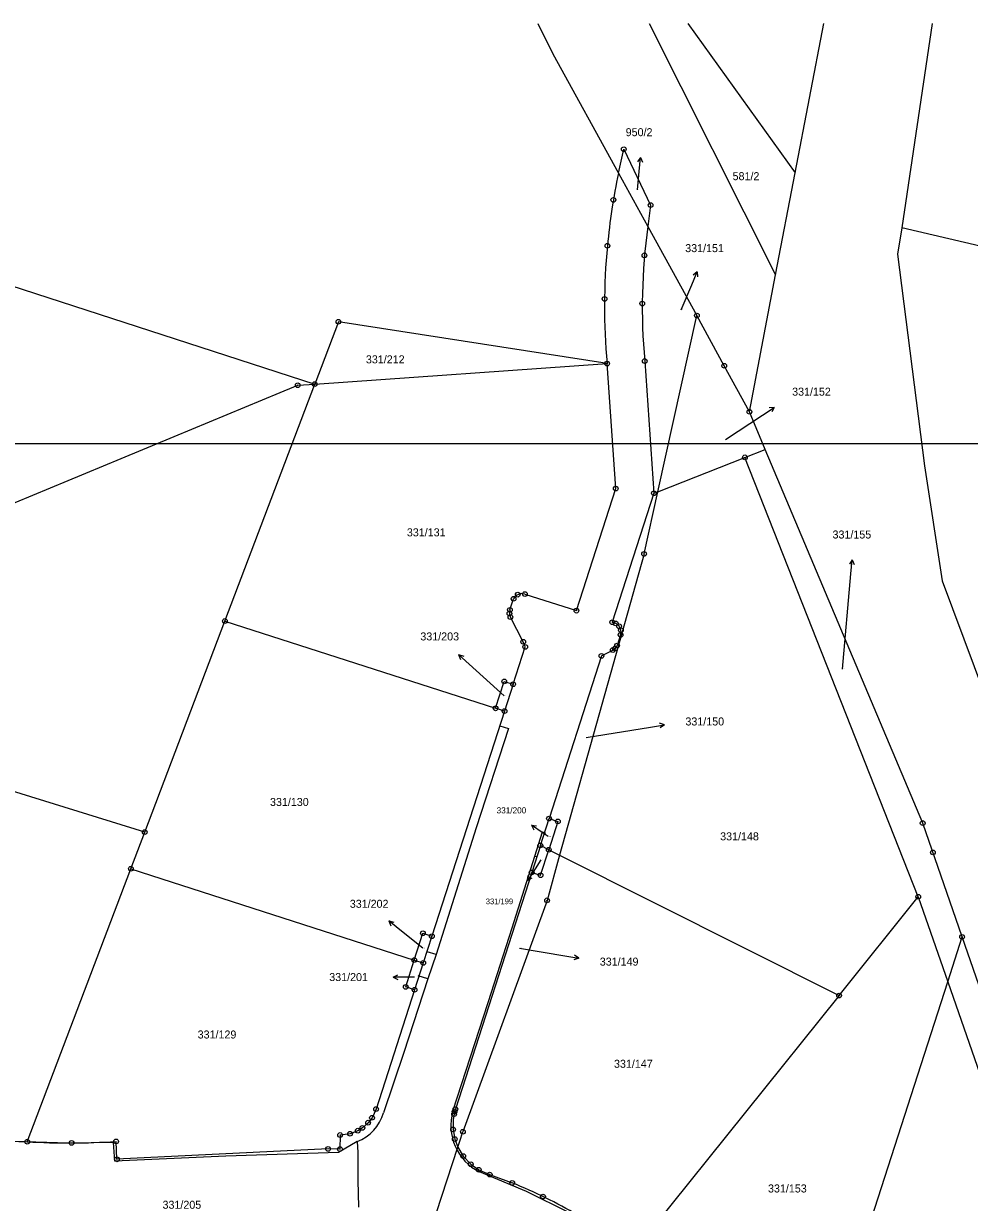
# Model space of a CAD drawing. Extents: x -770973 to -770265, y -1049936 to -1049427.
# Drawn here: x -770738 to -770637.6, y -1049553.2 to -1049428.1 of the extents above; entities that cross this region are included whole.
import ezdxf

# ---------------------------------------------------------------- set-up
doc = ezdxf.new("R2010")
doc.units = 0
for name, color, linetype in [('Vrstva 1', 7, 'Continuous'), ('Vrstva 13', 7, 'Continuous'), ('Vrstva 14', 7, 'Continuous'), ('Vrstva 16', 7, 'Continuous'), ('Vrstva 28', 7, 'Continuous'), ('Vrstva 50', 7, 'Continuous'), ('Vrstva 63', 7, 'Continuous')]:
    doc.layers.add(name, color=color, linetype=linetype)

msp = doc.modelspace()

# ---------------------------------------------------------------- linework, layer by layer
at = {"layer": 'Vrstva 1'}
for p, q in [((-770683.41, -1049428.06), (-770681.81, -1049431.27)), ((-770671.59, -1049428.06), (-770658.16, -1049454.74)), ((-770667.47, -1049428.06), (-770656.09, -1049443.91)), ((-770656.09, -1049443.91), (-770653.05, -1049428.06)), ((-770641.53, -1049428.06), (-770644.75, -1049449.76)), ((-770681.81, -1049431.27), (-770674.84, -1049443.93)), ((-770674.84, -1049443.93), (-770674.27, -1049441.4)), ((-770674.27, -1049441.4), (-770671.42, -1049447.33)), ((-770674.84, -1049443.93), (-770671.72, -1049449.6)), ((-770658.16, -1049454.74), (-770656.09, -1049443.91)), ((-770763.77, -1049447.98), (-770707.08, -1049466.34)), ((-770671.42, -1049447.33), (-770671.72, -1049449.6)), ((-770671.72, -1049449.6), (-770666.51, -1049459.06)), ((-770644.75, -1049449.76), (-770645.2, -1049452.54)), ((-770613.78, -1049456.97), (-770644.75, -1049449.76)), ((-770645.2, -1049452.54), (-770642.33, -1049475.02)), ((-770660.94, -1049469.28), (-770658.16, -1049454.74)), ((-770670.66, -1049477.77), (-770666.51, -1049459.06)), ((-770663.6, -1049464.4), (-770666.51, -1049459.06)), ((-770704.57, -1049459.72), (-770707.08, -1049466.34)), ((-770676.04, -1049464.17), (-770704.57, -1049459.72)), ((-770707.08, -1049466.34), (-770676.04, -1049464.17)), ((-770675.12, -1049477.44), (-770676.04, -1049464.17)), ((-770672.05, -1049463.89), (-770671.07, -1049477.93)), ((-770660.94, -1049469.28), (-770663.6, -1049464.4)), ((-770781.42, -1049496.53), (-770708.89, -1049466.46)), ((-770716.62, -1049491.5), (-770707.08, -1049466.34)), ((-770708.89, -1049466.46), (-770707.08, -1049466.34)), ((-770659.26, -1049473.27), (-770660.94, -1049469.28)), ((-770661.42, -1049474.12), (-770659.26, -1049473.27)), ((-770642.54, -1049512.96), (-770659.26, -1049473.27)), ((-770670.66, -1049477.77), (-770661.42, -1049474.12)), ((-770643.01, -1049520.78), (-770661.42, -1049474.12)), ((-770642.33, -1049475.02), (-770640.48, -1049487.25)), ((-770679.3, -1049490.4), (-770675.12, -1049477.44)), ((-770671.07, -1049477.93), (-770675.49, -1049491.63)), ((-770672.12, -1049484.38), (-770670.66, -1049477.77)), ((-770671.07, -1049477.93), (-770670.66, -1049477.77)), ((-770672.12, -1049484.38), (-770681.08, -1049516.37)), ((-770640.48, -1049487.25), (-770634.36, -1049503.66)), ((-770686.36, -1049490.32), (-770685.97, -1049489.14)), ((-770684.77, -1049488.64), (-770679.3, -1049490.4)), ((-770725.13, -1049513.91), (-770716.62, -1049491.5)), ((-770716.62, -1049491.5), (-770687.88, -1049500.77)), ((-770684.95, -1049493.71), (-770686.3, -1049491.08)), ((-770674.61, -1049492.97), (-770674.98, -1049494.11)), ((-770686.02, -1049498.21), (-770684.74, -1049494.25)), ((-770684.74, -1049494.25), (-770684.95, -1049493.71)), ((-770676.64, -1049495.2), (-770675.44, -1049494.58)), ((-770676.64, -1049495.2), (-770682.21, -1049512.48)), ((-770687.88, -1049500.77), (-770686.96, -1049497.91)), ((-770686.96, -1049497.91), (-770686.02, -1049498.21)), ((-770686.02, -1049498.21), (-770686.93, -1049501.07)), ((-770686.93, -1049501.07), (-770687.88, -1049500.77)), ((-770686.93, -1049501.07), (-770694.65, -1049524.97)), ((-770725.13, -1049513.91), (-770758.02, -1049503.75)), ((-770683.13, -1049515.33), (-770682.21, -1049512.48)), ((-770681.27, -1049512.78), (-770682.23, -1049515.79)), ((-770682.21, -1049512.48), (-770681.27, -1049512.78)), ((-770638.35, -1049525.05), (-770642.54, -1049512.96)), ((-770726.6, -1049517.8), (-770725.13, -1049513.91)), ((-770683.13, -1049515.33), (-770684.05, -1049518.19)), ((-770682.23, -1049515.79), (-770683.13, -1049515.33)), ((-770683.1, -1049518.49), (-770682.23, -1049515.79)), ((-770682.23, -1049515.79), (-770681.08, -1049516.37)), ((-770681.08, -1049516.37), (-770682.42, -1049521.16)), ((-770681.08, -1049516.37), (-770651.42, -1049531.27)), ((-770737.6, -1049546.8), (-770726.6, -1049517.8)), ((-770726.6, -1049517.8), (-770696.51, -1049527.5)), ((-770684.05, -1049518.19), (-770692.15, -1049543.32)), ((-770684.05, -1049518.19), (-770683.1, -1049518.49)), ((-770651.42, -1049531.27), (-770643.01, -1049520.78)), ((-770643.01, -1049520.78), (-770639.88, -1049529.8)), ((-770682.42, -1049521.16), (-770691.35, -1049545.73)), ((-770696.51, -1049527.5), (-770695.6, -1049524.66)), ((-770695.6, -1049524.66), (-770694.65, -1049524.97)), ((-770694.65, -1049524.97), (-770695.56, -1049527.8)), ((-770639.88, -1049529.8), (-770638.35, -1049525.05)), ((-770629.03, -1049551.97), (-770638.35, -1049525.05)), ((-770697.42, -1049530.36), (-770696.51, -1049527.5)), ((-770696.51, -1049527.5), (-770695.56, -1049527.8)), ((-770695.56, -1049527.8), (-770696.48, -1049530.66)), ((-770696.48, -1049530.66), (-770700.56, -1049543.32)), ((-770696.48, -1049530.66), (-770697.42, -1049530.36)), ((-770652.75, -1049569.77), (-770639.88, -1049529.8)), ((-770639.88, -1049529.8), (-770631.77, -1049553.2)), ((-770651.42, -1049531.27), (-770673.36, -1049558.61)), ((-770700.56, -1049543.32), (-770701, -1049544.25)), ((-770701, -1049544.25), (-770701.41, -1049544.77)), ((-770692.39, -1049544.43), (-770692.4, -1049545.48)), ((-770692.28, -1049543.86), (-770692.39, -1049544.43)), ((-770703.33, -1049545.94), (-770704.39, -1049546.08)), ((-770702.51, -1049545.62), (-770703.33, -1049545.94)), ((-770702.02, -1049545.32), (-770702.51, -1049545.62)), ((-770701.41, -1049544.77), (-770702.02, -1049545.32)), ((-770692.4, -1049545.48), (-770692.21, -1049546.51)), ((-770691.69, -1049546.75), (-770691.35, -1049545.73)), ((-770728.08, -1049548.66), (-770728.17, -1049546.76)), ((-770704.39, -1049546.08), (-770704.4, -1049547.58)), ((-770692.21, -1049546.51), (-770691.9, -1049547.38)), ((-770691.9, -1049547.38), (-770691.69, -1049546.75)), ((-770705.66, -1049547.56), (-770728.08, -1049548.66)), ((-770704.4, -1049547.58), (-770705.66, -1049547.56)), ((-770694.96, -1049556.73), (-770691.9, -1049547.38)), ((-770691.9, -1049547.38), (-770691.31, -1049548.32)), ((-770691.31, -1049548.32), (-770690.51, -1049549.18)), ((-770690.51, -1049549.18), (-770689.67, -1049549.77)), ((-770689.67, -1049549.77), (-770688.51, -1049550.28)), ((-770688.51, -1049550.28), (-770686.12, -1049551.16))]:
    msp.add_line(p, q, dxfattribs=at)
for centre, radius, start, end in [((-770609.84, -1049457.72), 66.44, 168.0204, 174.7659), ((-770609.76, -1049458.18), 62.55, 172.116, 185.2382), ((-770608.57, -1049458.08), 67.75, 174.5651, 185.1601), ((-770685.08, -1049489.59), 1, 72.1339, 153.1059), ((-770685.46, -1049490.63), 0.951, 160.8738, 208.1542), ((-770675.67, -1049492.76), 1.14, 38.3729, 81.1142), ((-770675.5, -1049492.65), 0.945, 340.255, 39.4766), ((-770675.83, -1049493.74), 0.926, 294.8238, 336.4083), ((-770689.65, -1049544.21), 2.65, 160.4513, 172.477), ((-770733.4, -1049469.63), 77.29, 256.2526, 266.8876), ((-770733.22, -1049467.42), 79.5, 266.8431, 273.643), ((-770705.43, -1049599.12), 51.7, 59.4615, 68.0688)]:
    msp.add_arc(centre, radius, start, end, dxfattribs=at)
at = {"layer": 'Vrstva 13'}
for p, q in [((-770672.82, -1049445.71), (-770672.64, -1049443.76)), ((-770668.19, -1049458.47), (-770667.05, -1049455.79)), ((-770663.48, -1049472.21), (-770659.54, -1049469.63)), ((-770651.05, -1049496.6), (-770650.15, -1049486.48)), ((-770686.98, -1049499.46), (-770690.7, -1049496.08)), ((-770678.28, -1049503.88), (-770671.43, -1049502.77)), ((-770682.29, -1049514.39), (-770682.84, -1049514.02)), ((-770683.08, -1049516.85), (-770683.69, -1049517.8)), ((-770695.61, -1049526.24), (-770698.05, -1049524.29)), ((-770685.35, -1049526.25), (-770680.52, -1049527.05)), ((-770696.5, -1049529.31), (-770697.26, -1049529.31))]:
    msp.add_line(p, q, dxfattribs=at)
at = {"layer": 'Vrstva 16'}
for p, q in [((-770672.51, -1049442.27), (-770672.8, -1049442.74)), ((-770672.64, -1049443.76), (-770672.51, -1049442.27)), ((-770672.51, -1049442.27), (-770672.3, -1049442.79)), ((-770667.05, -1049455.79), (-770666.47, -1049454.41)), ((-770666.47, -1049454.41), (-770666.89, -1049454.77)), ((-770666.47, -1049454.41), (-770666.43, -1049454.97)), ((-770659.54, -1049469.63), (-770658.29, -1049468.81)), ((-770658.29, -1049468.81), (-770658.84, -1049468.87)), ((-770658.29, -1049468.81), (-770658.57, -1049469.29)), ((-770650.02, -1049484.99), (-770650.31, -1049485.46)), ((-770650.15, -1049486.48), (-770650.02, -1049484.99)), ((-770650.02, -1049484.99), (-770649.81, -1049485.51)), ((-770690.7, -1049496.08), (-770691.81, -1049495.07)), ((-770691.81, -1049495.07), (-770691.61, -1049495.59)), ((-770691.81, -1049495.07), (-770691.27, -1049495.22)), ((-770671.43, -1049502.77), (-770669.95, -1049502.53)), ((-770669.95, -1049502.53), (-770670.48, -1049502.36)), ((-770669.95, -1049502.53), (-770670.4, -1049502.86)), ((-770682.84, -1049514.02), (-770684.08, -1049513.18)), ((-770684.08, -1049513.18), (-770683.81, -1049513.67)), ((-770684.08, -1049513.18), (-770683.53, -1049513.25)), ((-770683.69, -1049517.8), (-770684.49, -1049519.07)), ((-770684.49, -1049519.07), (-770684.44, -1049518.51)), ((-770684.49, -1049519.07), (-770684.01, -1049518.78)), ((-770698.05, -1049524.29), (-770699.22, -1049523.35)), ((-770699.22, -1049523.35), (-770698.99, -1049523.86)), ((-770699.22, -1049523.35), (-770698.67, -1049523.47)), ((-770680.52, -1049527.05), (-770679.04, -1049527.3)), ((-770679.04, -1049527.3), (-770679.49, -1049526.97)), ((-770679.04, -1049527.3), (-770679.57, -1049527.46)), ((-770698.76, -1049529.31), (-770698.26, -1049529.06)), ((-770697.26, -1049529.31), (-770698.76, -1049529.31)), ((-770698.76, -1049529.31), (-770698.26, -1049529.56))]:
    msp.add_line(p, q, dxfattribs=at)
at = {"layer": 'Vrstva 28'}
for centre, radius in [((-770674.27, -1049441.4), 0.25), ((-770674.27, -1049441.4), 0.005), ((-770675.38, -1049446.78), 0.25), ((-770675.38, -1049446.78), 0.005), ((-770671.42, -1049447.33), 0.25), ((-770671.42, -1049447.33), 0.005), ((-770676.01, -1049451.66), 0.25), ((-770676.01, -1049451.66), 0.005), ((-770672.08, -1049452.67), 0.25), ((-770672.08, -1049452.67), 0.005), ((-770676.31, -1049457.29), 0.25), ((-770676.31, -1049457.29), 0.005), ((-770672.31, -1049457.79), 0.25), ((-770672.31, -1049457.79), 0.005), ((-770704.57, -1049459.72), 0.25), ((-770666.51, -1049459.06), 0.25), ((-770666.51, -1049459.06), 0.005), ((-770704.57, -1049459.72), 0.005), ((-770676.04, -1049464.17), 0.25), ((-770676.04, -1049464.17), 0.005), ((-770672.05, -1049463.89), 0.25), ((-770672.05, -1049463.89), 0.005), ((-770663.6, -1049464.4), 0.25), ((-770663.6, -1049464.4), 0.005), ((-770708.89, -1049466.46), 0.25), ((-770708.89, -1049466.46), 0.005), ((-770707.08, -1049466.34), 0.25), ((-770707.08, -1049466.34), 0.005), ((-770660.94, -1049469.28), 0.25), ((-770660.94, -1049469.28), 0.005), ((-770661.42, -1049474.12), 0.25), ((-770661.42, -1049474.12), 0.005), ((-770675.12, -1049477.44), 0.25), ((-770675.12, -1049477.44), 0.005), ((-770671.07, -1049477.93), 0.25), ((-770671.07, -1049477.93), 0.005), ((-770672.12, -1049484.38), 0.25), ((-770672.12, -1049484.38), 0.005), ((-770684.77, -1049488.64), 0.25), ((-770685.97, -1049489.14), 0.25), ((-770685.97, -1049489.14), 0.005), ((-770685.53, -1049488.7), 0.25), ((-770685.53, -1049488.7), 0.005), ((-770684.77, -1049488.64), 0.005), ((-770686.41, -1049490.7), 0.25), ((-770686.36, -1049490.32), 0.25), ((-770686.3, -1049491.08), 0.25), ((-770686.41, -1049490.7), 0.005), ((-770686.36, -1049490.32), 0.005), ((-770679.3, -1049490.4), 0.25), ((-770679.3, -1049490.4), 0.005), ((-770716.62, -1049491.5), 0.25), ((-770716.62, -1049491.5), 0.005), ((-770686.3, -1049491.08), 0.005), ((-770675.49, -1049491.63), 0.25), ((-770675.49, -1049491.63), 0.005), ((-770675.13, -1049491.75), 0.25), ((-770675.13, -1049491.75), 0.005), ((-770674.77, -1049492.05), 0.25), ((-770674.77, -1049492.05), 0.005), ((-770674.61, -1049492.97), 0.25), ((-770674.57, -1049492.48), 0.25), ((-770674.61, -1049492.97), 0.005), ((-770674.57, -1049492.48), 0.005), ((-770684.95, -1049493.71), 0.25), ((-770684.74, -1049494.25), 0.25), ((-770684.95, -1049493.71), 0.005), ((-770684.74, -1049494.25), 0.005), ((-770675.44, -1049494.58), 0.25), ((-770675.19, -1049494.41), 0.25), ((-770675.44, -1049494.58), 0.005), ((-770674.98, -1049494.11), 0.25), ((-770675.19, -1049494.41), 0.005), ((-770674.98, -1049494.11), 0.005), ((-770676.64, -1049495.2), 0.25), ((-770676.64, -1049495.2), 0.005), ((-770686.96, -1049497.91), 0.25), ((-770686.96, -1049497.91), 0.005), ((-770686.02, -1049498.21), 0.25), ((-770686.02, -1049498.21), 0.005), ((-770687.88, -1049500.77), 0.25), ((-770687.88, -1049500.77), 0.005), ((-770686.93, -1049501.07), 0.25), ((-770686.93, -1049501.07), 0.005), ((-770682.21, -1049512.48), 0.25), ((-770682.21, -1049512.48), 0.005), ((-770681.27, -1049512.78), 0.25), ((-770681.27, -1049512.78), 0.005), ((-770642.54, -1049512.96), 0.25), ((-770642.54, -1049512.96), 0.005), ((-770725.13, -1049513.91), 0.25), ((-770725.13, -1049513.91), 0.005), ((-770683.13, -1049515.33), 0.25), ((-770683.13, -1049515.33), 0.005), ((-770682.23, -1049515.79), 0.25), ((-770682.23, -1049515.79), 0.005), ((-770641.46, -1049516.07), 0.25), ((-770641.46, -1049516.07), 0.005), ((-770726.6, -1049517.8), 0.25), ((-770726.6, -1049517.8), 0.005), ((-770684.05, -1049518.19), 0.25), ((-770684.05, -1049518.19), 0.005), ((-770683.1, -1049518.49), 0.25), ((-770683.1, -1049518.49), 0.005), ((-770682.42, -1049521.16), 0.25), ((-770643.01, -1049520.78), 0.25), ((-770643.01, -1049520.78), 0.005), ((-770682.42, -1049521.16), 0.005), ((-770695.6, -1049524.66), 0.25), ((-770695.6, -1049524.66), 0.005), ((-770694.65, -1049524.97), 0.25), ((-770694.65, -1049524.97), 0.005), ((-770638.35, -1049525.05), 0.25), ((-770638.35, -1049525.05), 0.005), ((-770696.51, -1049527.5), 0.25), ((-770696.51, -1049527.5), 0.005), ((-770695.56, -1049527.8), 0.25), ((-770695.56, -1049527.8), 0.005), ((-770697.42, -1049530.36), 0.25), ((-770697.42, -1049530.36), 0.005), ((-770696.48, -1049530.66), 0.25), ((-770696.48, -1049530.66), 0.005), ((-770651.42, -1049531.27), 0.25), ((-770651.42, -1049531.27), 0.005), ((-770700.56, -1049543.32), 0.25), ((-770700.56, -1049543.32), 0.005), ((-770692.23, -1049543.59), 0.25), ((-770692.15, -1049543.32), 0.25), ((-770692.15, -1049543.32), 0.005), ((-770701.41, -1049544.77), 0.25), ((-770701, -1049544.25), 0.25), ((-770701, -1049544.25), 0.005), ((-770692.28, -1049543.86), 0.25), ((-770692.28, -1049543.86), 0.005), ((-770692.23, -1049543.59), 0.005), ((-770704.39, -1049546.08), 0.25), ((-770703.33, -1049545.94), 0.25), ((-770703.33, -1049545.94), 0.005), ((-770702.51, -1049545.62), 0.25), ((-770702.51, -1049545.62), 0.005), ((-770702.02, -1049545.32), 0.25), ((-770702.02, -1049545.32), 0.005), ((-770701.41, -1049544.77), 0.005), ((-770692.4, -1049545.48), 0.25), ((-770692.4, -1049545.48), 0.005), ((-770691.35, -1049545.73), 0.25), ((-770691.35, -1049545.73), 0.005), ((-770737.6, -1049546.8), 0.25), ((-770737.6, -1049546.8), 0.005), ((-770732.9, -1049546.92), 0.25), ((-770732.9, -1049546.92), 0.005), ((-770728.17, -1049546.76), 0.25), ((-770728.17, -1049546.76), 0.005), ((-770704.39, -1049546.08), 0.005), ((-770692.21, -1049546.51), 0.25), ((-770692.21, -1049546.51), 0.005), ((-770728.08, -1049548.66), 0.25), ((-770705.66, -1049547.56), 0.25), ((-770705.66, -1049547.56), 0.005), ((-770704.4, -1049547.58), 0.25), ((-770704.4, -1049547.58), 0.005), ((-770691.31, -1049548.32), 0.25), ((-770691.31, -1049548.32), 0.005), ((-770728.08, -1049548.66), 0.005), ((-770690.51, -1049549.18), 0.25), ((-770690.51, -1049549.18), 0.005), ((-770689.67, -1049549.77), 0.25), ((-770689.67, -1049549.77), 0.005), ((-770688.51, -1049550.28), 0.25), ((-770688.51, -1049550.28), 0.005), ((-770686.12, -1049551.16), 0.25), ((-770686.12, -1049551.16), 0.005), ((-770682.85, -1049552.61), 0.25), ((-770682.85, -1049552.61), 0.005)]:
    msp.add_circle(centre, radius, dxfattribs=at)
at = {"layer": 'Vrstva 50'}
for p, q in [((-770686.5, -1049502.91), (-770689.93, -1049513.47)), ((-770687.44, -1049502.64), (-770686.5, -1049502.91)), ((-770689.93, -1049513.47), (-770694.19, -1049526.91)), ((-770683.71, -1049516.48), (-770682.91, -1049513.89)), ((-770682.91, -1049513.89), (-770682.57, -1049514.04)), ((-770686.13, -1049524.07), (-770683.71, -1049516.48)), ((-770683.71, -1049516.48), (-770683.46, -1049516.53)), ((-770688.68, -1049532.01), (-770686.13, -1049524.07)), ((-770694.19, -1049526.91), (-770695.16, -1049526.62)), ((-770694.19, -1049526.91), (-770695.08, -1049529.51)), ((-770695.08, -1049529.51), (-770697.62, -1049537.3)), ((-770695.08, -1049529.51), (-770696.11, -1049529.17)), ((-770692.42, -1049543.55), (-770688.68, -1049532.01)), ((-770697.62, -1049537.3), (-770699.79, -1049543.72)), ((-770733.22, -1049546.96), (-770739, -1049546.78)), ((-770728.46, -1049546.87), (-770733.22, -1049546.96)), ((-770728.3, -1049548.86), (-770728.46, -1049546.87)), ((-770702.56, -1049546.76), (-770704.55, -1049547.95)), ((-770702.56, -1049546.76), (-770702.51, -1049547.92)), ((-770716.53, -1049548.32), (-770728.3, -1049548.86)), ((-770704.55, -1049547.95), (-770716.53, -1049548.32)), ((-770702.51, -1049547.92), (-770702.49, -1049550.86)), ((-770702.49, -1049550.86), (-770702.44, -1049553.73)), ((-770684.59, -1049552.08), (-770689.6, -1049549.99)), ((-770680.05, -1049554.34), (-770684.59, -1049552.08))]:
    msp.add_line(p, q, dxfattribs=at)
for centre, radius, start, end in [((-770704.11, -1049542.57), 4.47, 290.2803, 345.0412), ((-770687.12, -1049545.07), 5.51, 164.0321, 243.264)]:
    msp.add_arc(centre, radius, start, end, dxfattribs=at)
at = {"layer": 'Vrstva 63'}
msp.add_lwpolyline([(-770858.67, -1049892.7), (-770264.67, -1049892.7), (-770264.67, -1049472.7), (-770858.67, -1049472.7), (-770858.67, -1049892.7)], dxfattribs=at)

# ---------------------------------------------------------------- texts
at = {"layer": 'Vrstva 14'}
for s, height, p in [('581/2', 0.85, (-770662.72, -1049444.69)), ('950/2', 0.05, (-770672.82, -1049445.71)), ('331/151', 0.05, (-770668.19, -1049458.47)), ('331/212', 0.85, (-770701.65, -1049464.14)), ('331/152', 0.05, (-770663.48, -1049472.21)), ('331/131', 0.85, (-770697.3, -1049482.51)), ('331/155', 0.05, (-770651.05, -1049496.6)), ('331/203', 0.05, (-770686.98, -1049499.46)), ('331/150', 0.05, (-770678.28, -1049503.88)), ('331/130', 0.85, (-770711.83, -1049511.14)), ('331/200', 0.05, (-770682.29, -1049514.39)), ('331/148', 0.85, (-770664.04, -1049514.79)), ('331/199', 0.05, (-770683.08, -1049516.85)), ('331/202', 0.05, (-770695.61, -1049526.24)), ('331/149', 0.05, (-770685.35, -1049526.25)), ('331/201', 0.05, (-770696.5, -1049529.31)), ('331/129', 0.85, (-770719.51, -1049535.83)), ('331/147', 0.85, (-770675.31, -1049538.94)), ('331/153', 0.85, (-770658.96, -1049552.18))]:
    msp.add_text(s, height=height, dxfattribs=at).set_placement(p)
at = {"layer": 'Vrstva 16'}
for s, height, p in [('950/2', 0.85, (-770674.07, -1049440.02)), ('331/151', 0.85, (-770667.75, -1049452.33)), ('331/152', 0.85, (-770656.4, -1049467.57)), ('331/155', 0.85, (-770652.11, -1049482.74)), ('331/203', 0.85, (-770695.87, -1049493.56)), ('331/150', 0.85, (-770667.73, -1049502.59)), ('331/200', 0.65, (-770687.77, -1049511.93)), ('331/199', 0.6, (-770688.92, -1049521.57)), ('331/202', 0.85, (-770703.36, -1049521.95)), ('331/149', 0.85, (-770676.82, -1049528.09)), ('331/201', 0.85, (-770705.54, -1049529.73)), ('331/205', 0.85, (-770723.24, -1049553.91))]:
    msp.add_text(s, height=height, dxfattribs=at).set_placement(p)

doc.saveas('drawing.dxf')
